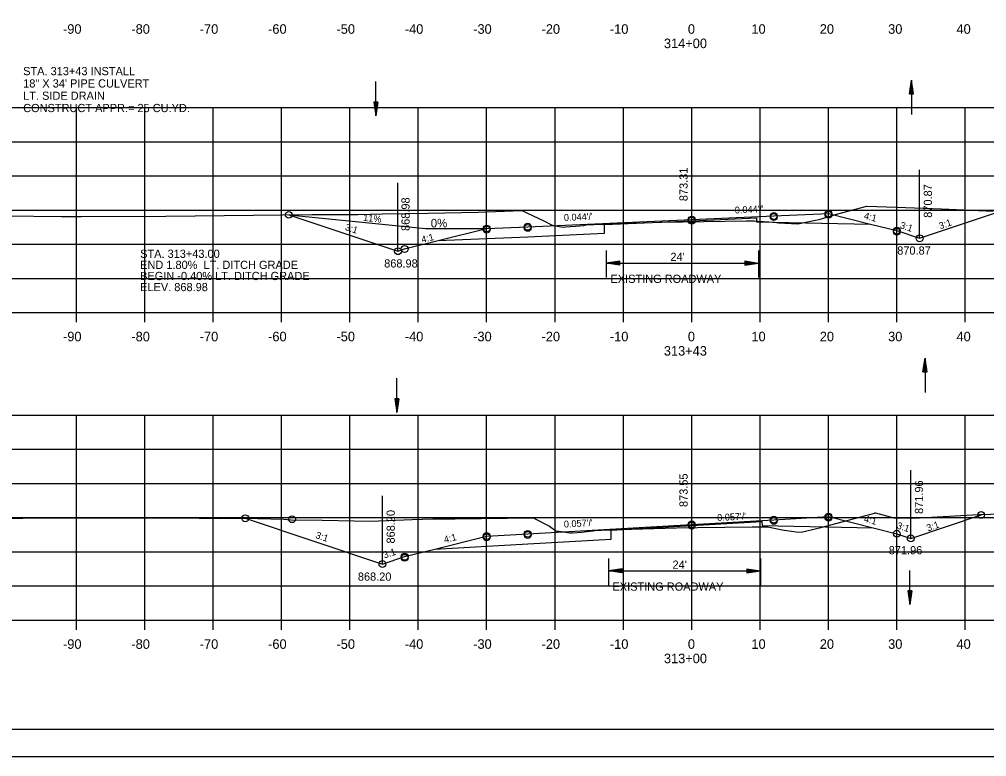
# Model space of a CAD drawing. Extents: x 1486524 to 1499135, y 326561 to 337924.
# Drawn here: x 1488884.5 to 1489026, y 335339.4 to 335447.3 of the extents above; entities that cross this region are included whole.
import ezdxf

# ---------------------------------------------------------------- set-up
doc = ezdxf.new("R2010")
doc.units = 0
for name, color, linetype in [('Default', 7, 'Continuous'), ('E_Const Align', 7, 'Continuous'), ('E_Const Align Station', 7, 'Continuous'), ('E_Ownership Information', 7, 'Continuous'), ('E_Property Line', 7, 'Continuous'), ('E_Proposed ROW and Easements', 7, 'Continuous'), ('E_Proposed ROW Fig Annot', 7, 'Continuous'), ('E_Quarter Calls', 7, 'Continuous'), ('E_Station Offset', 7, 'Continuous'), ('E_Survey Point', 7, 'Continuous'), ('E_Title Sheet', 7, 'Continuous'), ('E_Tract Number', 7, 'Continuous'), ('R_Water Annot', 7, 'Continuous'), ('R_Xsect Elev', 7, 'Continuous'), ('R_Xsect Slope', 7, 'Continuous')]:
    doc.layers.add(name, color=color, linetype=linetype)

msp = doc.modelspace()

# ---------------------------------------------------------------- linework, layer by layer
at = {"layer": 'E_Const Align'}
for p, q in [((1488842.89, 335404.34), (1489122.89, 335404.34)), ((1488892.89, 335402.94), (1488892.89, 335404.34)), ((1488902.89, 335402.94), (1488902.89, 335404.34)), ((1488912.89, 335402.94), (1488912.89, 335404.34)), ((1488922.89, 335402.94), (1488922.89, 335404.34)), ((1488932.89, 335402.94), (1488932.89, 335404.34)), ((1488942.89, 335402.94), (1488942.89, 335404.34)), ((1488952.89, 335402.94), (1488952.89, 335404.34)), ((1488962.89, 335402.94), (1488962.89, 335404.34)), ((1488972.89, 335402.94), (1488972.89, 335404.34)), ((1488982.89, 335402.94), (1488982.89, 335404.34)), ((1488992.89, 335402.94), (1488992.89, 335404.34)), ((1489002.89, 335402.94), (1489002.89, 335404.34)), ((1489012.89, 335402.94), (1489012.89, 335404.34)), ((1489022.89, 335402.94), (1489022.89, 335404.34)), ((1488842.89, 335359.34), (1489122.89, 335359.34)), ((1488892.89, 335357.94), (1488892.89, 335359.34)), ((1488902.89, 335357.94), (1488902.89, 335359.34)), ((1488912.89, 335357.94), (1488912.89, 335359.34)), ((1488922.89, 335357.94), (1488922.89, 335359.34)), ((1488932.89, 335357.94), (1488932.89, 335359.34)), ((1488942.89, 335357.94), (1488942.89, 335359.34)), ((1488952.89, 335357.94), (1488952.89, 335359.34)), ((1488962.89, 335357.94), (1488962.89, 335359.34)), ((1488972.89, 335357.94), (1488972.89, 335359.34)), ((1488982.89, 335357.94), (1488982.89, 335359.34)), ((1488992.89, 335357.94), (1488992.89, 335359.34)), ((1489002.89, 335357.94), (1489002.89, 335359.34)), ((1489012.89, 335357.94), (1489012.89, 335359.34)), ((1489022.89, 335357.94), (1489022.89, 335359.34))]:
    msp.add_line(p, q, dxfattribs=at)
at = {"layer": 'E_Ownership Information'}
for p, q in [((1488842.89, 335434.34), (1489122.89, 335434.34)), ((1488892.89, 335404.34), (1488892.89, 335434.34)), ((1488902.89, 335404.34), (1488902.89, 335434.34)), ((1488912.89, 335404.34), (1488912.89, 335434.34)), ((1488922.89, 335404.34), (1488922.89, 335434.34)), ((1488932.89, 335404.34), (1488932.89, 335434.34)), ((1488942.89, 335404.34), (1488942.89, 335434.34)), ((1488952.89, 335404.34), (1488952.89, 335434.34)), ((1488962.89, 335404.34), (1488962.89, 335434.34)), ((1488972.89, 335404.34), (1488972.89, 335434.34)), ((1488982.89, 335404.34), (1488982.89, 335434.34)), ((1488992.89, 335404.34), (1488992.89, 335434.34)), ((1489002.89, 335404.34), (1489002.89, 335434.34)), ((1489012.89, 335404.34), (1489012.89, 335434.34)), ((1489022.89, 335404.34), (1489022.89, 335434.34)), ((1488842.89, 335429.34), (1489122.89, 335429.34)), ((1488842.89, 335424.34), (1489122.89, 335424.34)), ((1488842.89, 335419.34), (1489122.89, 335419.34)), ((1488842.89, 335414.34), (1489122.89, 335414.34)), ((1488842.89, 335409.34), (1489122.89, 335409.34)), ((1488842.89, 335404.34), (1489122.89, 335404.34)), ((1488842.89, 335389.34), (1489122.89, 335389.34)), ((1488892.89, 335359.34), (1488892.89, 335389.34)), ((1488902.89, 335359.34), (1488902.89, 335389.34)), ((1488912.89, 335359.34), (1488912.89, 335389.34)), ((1488922.89, 335359.34), (1488922.89, 335389.34)), ((1488932.89, 335359.34), (1488932.89, 335389.34)), ((1488942.89, 335359.34), (1488942.89, 335389.34)), ((1488952.89, 335359.34), (1488952.89, 335389.34)), ((1488962.89, 335359.34), (1488962.89, 335389.34)), ((1488972.89, 335359.34), (1488972.89, 335389.34)), ((1488982.89, 335359.34), (1488982.89, 335389.34)), ((1488992.89, 335359.34), (1488992.89, 335389.34)), ((1489002.89, 335359.34), (1489002.89, 335389.34)), ((1489012.89, 335359.34), (1489012.89, 335389.34)), ((1489022.89, 335359.34), (1489022.89, 335389.34)), ((1488842.89, 335384.34), (1489122.89, 335384.34)), ((1488842.89, 335379.34), (1489122.89, 335379.34)), ((1488842.89, 335374.34), (1489122.89, 335374.34)), ((1488842.89, 335369.34), (1489122.89, 335369.34)), ((1488842.89, 335364.34), (1489122.89, 335364.34)), ((1488842.89, 335359.34), (1489122.89, 335359.34))]:
    msp.add_line(p, q, dxfattribs=at)
at = {"layer": 'E_Property Line'}
msp.add_line((1489141.07, 335343.34), (1488824.89, 335343.34), dxfattribs=at)
at = {"layer": 'E_Proposed ROW and Easements'}
for p, q in [((1488970.38, 335413.41), (1488970.38, 335409.48)), ((1488992.66, 335413.41), (1488992.66, 335409.48)), ((1488972.38, 335411.89), (1488970.38, 335411.59)), ((1488972.38, 335411.29), (1488970.38, 335411.59)), ((1488972.38, 335411.84), (1488970.71, 335411.59)), ((1488972.38, 335411.34), (1488970.71, 335411.59)), ((1488972.38, 335411.79), (1488971.06, 335411.59)), ((1488972.38, 335411.4), (1488971.06, 335411.59)), ((1488972.38, 335411.74), (1488971.39, 335411.59)), ((1488972.38, 335411.45), (1488971.39, 335411.59)), ((1488972.38, 335411.69), (1488971.73, 335411.59)), ((1488972.38, 335411.5), (1488971.73, 335411.59)), ((1488972.38, 335411.64), (1488972.06, 335411.59)), ((1488972.38, 335411.55), (1488972.06, 335411.59)), ((1488972.38, 335411.29), (1488972.38, 335411.89)), ((1488990.66, 335411.9), (1488992.66, 335411.6)), ((1488990.66, 335411.9), (1488990.66, 335411.3)), ((1488990.66, 335411.85), (1488992.32, 335411.6)), ((1488990.66, 335411.8), (1488991.98, 335411.6)), ((1488990.66, 335411.75), (1488991.65, 335411.6)), ((1488990.66, 335411.7), (1488991.31, 335411.6)), ((1488990.66, 335411.65), (1488990.97, 335411.6)), ((1488990.66, 335411.3), (1488992.66, 335411.6)), ((1488990.66, 335411.5), (1488991.31, 335411.6)), ((1488990.66, 335411.4), (1488991.98, 335411.6)), ((1488990.66, 335411.35), (1488992.32, 335411.6)), ((1488990.66, 335411.45), (1488991.65, 335411.6)), ((1488990.66, 335411.55), (1488990.97, 335411.6)), ((1488970.69, 335368.37), (1488970.69, 335364.44)), ((1488992.96, 335368.37), (1488992.96, 335364.44)), ((1488972.69, 335366.85), (1488970.69, 335366.55)), ((1488972.69, 335366.8), (1488971.02, 335366.55)), ((1488972.69, 335366.75), (1488971.37, 335366.55)), ((1488972.69, 335366.25), (1488972.69, 335366.85)), ((1488990.96, 335366.86), (1488992.96, 335366.56)), ((1488990.96, 335366.86), (1488990.96, 335366.26)), ((1488990.96, 335366.81), (1488992.63, 335366.56)), ((1488990.96, 335366.76), (1488992.29, 335366.56)), ((1488972.69, 335366.25), (1488970.69, 335366.55)), ((1488972.69, 335366.3), (1488971.02, 335366.55)), ((1488972.69, 335366.35), (1488971.37, 335366.55)), ((1488972.69, 335366.7), (1488971.7, 335366.55)), ((1488972.69, 335366.4), (1488971.7, 335366.55)), ((1488972.69, 335366.65), (1488972.04, 335366.55)), ((1488972.69, 335366.46), (1488972.04, 335366.55)), ((1488972.69, 335366.6), (1488972.37, 335366.55)), ((1488972.69, 335366.51), (1488972.37, 335366.55)), ((1488990.96, 335366.71), (1488991.95, 335366.56)), ((1488990.96, 335366.65), (1488991.61, 335366.56)), ((1488990.96, 335366.6), (1488991.28, 335366.56)), ((1488990.96, 335366.26), (1488992.96, 335366.56)), ((1488990.96, 335366.46), (1488991.61, 335366.56)), ((1488990.96, 335366.36), (1488992.29, 335366.56)), ((1488990.96, 335366.31), (1488992.63, 335366.56)), ((1488990.96, 335366.41), (1488991.95, 335366.56)), ((1488990.96, 335366.51), (1488991.28, 335366.56))]:
    msp.add_line(p, q, dxfattribs=at)
at = {"layer": 'E_Proposed ROW Fig Annot'}
for p, q in [((1489014.73, 335436.34), (1489015.03, 335438.34)), ((1489014.78, 335436.34), (1489015.03, 335438.01)), ((1489014.83, 335436.34), (1489015.03, 335437.67)), ((1489015.33, 335436.34), (1489015.03, 335438.34)), ((1489015.28, 335436.34), (1489015.03, 335438.01)), ((1489015.23, 335436.34), (1489015.03, 335437.67)), ((1489014.73, 335436.34), (1489015.33, 335436.34)), ((1489014.88, 335436.34), (1489015.03, 335437.33)), ((1489014.93, 335436.34), (1489015.03, 335436.99)), ((1489014.98, 335436.34), (1489015.03, 335436.66)), ((1489015.18, 335436.34), (1489015.03, 335437.33)), ((1489015.13, 335436.34), (1489015.03, 335436.99)), ((1489015.08, 335436.34), (1489015.03, 335436.66)), ((1488936.37, 335435.15), (1488936.67, 335433.15)), ((1488936.97, 335435.15), (1488936.37, 335435.15)), ((1488936.42, 335435.15), (1488936.67, 335433.49)), ((1488936.47, 335435.15), (1488936.67, 335433.83)), ((1488936.52, 335435.15), (1488936.67, 335434.16)), ((1488936.57, 335435.15), (1488936.67, 335434.5)), ((1488936.62, 335435.15), (1488936.67, 335434.84)), ((1488936.97, 335435.15), (1488936.67, 335433.15)), ((1488936.77, 335435.15), (1488936.67, 335434.5)), ((1488936.87, 335435.15), (1488936.67, 335433.83)), ((1488936.92, 335435.15), (1488936.67, 335433.49)), ((1488936.82, 335435.15), (1488936.67, 335434.16)), ((1488936.72, 335435.15), (1488936.67, 335434.84)), ((1488970.38, 335411.59), (1488992.66, 335411.6)), ((1489016.72, 335395.67), (1489017.02, 335397.67)), ((1489016.77, 335395.67), (1489017.02, 335397.33)), ((1489016.82, 335395.67), (1489017.02, 335396.99)), ((1489016.87, 335395.67), (1489017.02, 335396.66)), ((1489017.32, 335395.67), (1489017.02, 335397.67)), ((1489017.27, 335395.67), (1489017.02, 335397.33)), ((1489017.22, 335395.67), (1489017.02, 335396.99)), ((1489017.17, 335395.67), (1489017.02, 335396.66)), ((1489016.72, 335395.67), (1489017.32, 335395.67)), ((1489016.92, 335395.67), (1489017.02, 335396.32)), ((1489016.97, 335395.67), (1489017.02, 335395.98)), ((1489017.11, 335395.67), (1489017.02, 335396.32)), ((1489017.06, 335395.67), (1489017.02, 335395.98)), ((1488939.44, 335391.73), (1488939.74, 335389.73)), ((1488940.04, 335391.73), (1488939.44, 335391.73)), ((1488939.49, 335391.73), (1488939.74, 335390.06)), ((1488939.54, 335391.73), (1488939.74, 335390.41)), ((1488939.59, 335391.73), (1488939.74, 335390.74)), ((1488939.64, 335391.73), (1488939.74, 335391.08)), ((1488939.69, 335391.73), (1488939.74, 335391.41)), ((1488940.04, 335391.73), (1488939.74, 335389.73)), ((1488939.83, 335391.73), (1488939.74, 335391.08)), ((1488939.94, 335391.73), (1488939.74, 335390.41)), ((1488939.99, 335391.73), (1488939.74, 335390.06)), ((1488939.89, 335391.73), (1488939.74, 335390.74)), ((1488939.78, 335391.73), (1488939.74, 335391.41)), ((1488970.69, 335366.55), (1488992.96, 335366.56)), ((1489014.49, 335363.62), (1489014.79, 335361.62)), ((1489015.09, 335363.62), (1489014.49, 335363.62)), ((1489014.54, 335363.62), (1489014.79, 335361.95)), ((1489014.59, 335363.62), (1489014.79, 335362.29)), ((1489014.64, 335363.62), (1489014.79, 335362.63)), ((1489014.69, 335363.62), (1489014.79, 335362.97)), ((1489014.74, 335363.62), (1489014.79, 335363.3)), ((1489015.09, 335363.62), (1489014.79, 335361.62)), ((1489014.89, 335363.62), (1489014.79, 335362.97)), ((1489014.99, 335363.62), (1489014.79, 335362.29)), ((1489015.04, 335363.62), (1489014.79, 335361.95)), ((1489014.94, 335363.62), (1489014.79, 335362.63)), ((1489014.84, 335363.62), (1489014.79, 335363.3))]:
    msp.add_line(p, q, dxfattribs=at)
at = {"layer": 'E_Quarter Calls'}
msp.add_line((1488812.48, 335339.37), (1489145.82, 335339.37), dxfattribs=at)
for points in [[(1488812.48, 335552.7), (1489145.82, 335552.7), (1489145.82, 335339.36), (1488812.48, 335339.36)], [(1489058.81, 335548.8), (1489058.81, 335538.92), (1489094.54, 335538.92), (1489094.54, 335536), (1489117.74, 335536), (1489117.74, 335511.67), (1489141.07, 335511.67), (1489141.07, 335343.34), (1488824.89, 335343.34), (1488824.89, 335548.8)]]:
    msp.add_lwpolyline(points, close=True, dxfattribs=at)
for centre in [(1488923.94, 335418.65), (1489002.89, 335418.84), (1489002.89, 335418.84), (1489002.89, 335418.67), (1488982.89, 335417.96), (1488982.89, 335417.96), (1488982.89, 335417.79), (1488994.89, 335418.49), (1488994.89, 335418.49), (1488994.89, 335418.32), (1488952.89, 335416.65), (1488952.89, 335416.65), (1488952.89, 335416.48), (1488958.89, 335416.91), (1488958.89, 335416.91), (1488958.89, 335416.74), (1489012.89, 335416.34), (1489012.89, 335416.34), (1489012.89, 335416.17), (1489016.23, 335415.22), (1488939.92, 335413.32), (1488940.89, 335413.65), (1488940.89, 335413.65), (1489025.23, 335374.74), (1488917.58, 335374.24), (1488924.45, 335374.11), (1488982.89, 335373.34), (1488982.89, 335373.34), (1488994.89, 335374.03), (1488994.89, 335374.03), (1488994.89, 335373.86), (1489002.89, 335374.49), (1489002.89, 335374.49), (1489002.89, 335374.32), (1488958.89, 335371.97), (1488958.89, 335371.97), (1488982.89, 335373.17), (1489012.89, 335371.99), (1488952.89, 335371.63), (1488952.89, 335371.63), (1488952.89, 335371.46), (1488958.89, 335371.8), (1489014.93, 335371.3), (1488940.89, 335368.63), (1488940.89, 335368.63), (1488940.89, 335368.46), (1488937.65, 335367.55)]:
    msp.add_circle(centre, 0.5, dxfattribs=at)
at = {"layer": 'E_Station Offset'}
for p, q in [((1488923.94, 335418.65), (1488943.93, 335416.65)), ((1488943.93, 335416.65), (1488952.93, 335416.65))]:
    msp.add_line(p, q, dxfattribs=at)
at = {"layer": 'E_Survey Point'}
for points in [[(1488945.81, 335414.88), (1488958.89, 335415.45), (1488970.12, 335415.95), (1488970.12, 335417.24), (1488982.89, 335417.79), (1488992.37, 335418.21), (1488992.38, 335417.63), (1489009.06, 335417.29)], [(1488945.31, 335369.74), (1488958.89, 335370.51), (1488971.1, 335371.21), (1488971.1, 335372.5), (1488982.89, 335373.18), (1488993.16, 335373.76), (1488993.17, 335373.18), (1489009.41, 335372.85)]]:
    msp.add_lwpolyline(points, dxfattribs=at)
at = {"layer": 'E_Title Sheet'}
for points in [[(1488923.94, 335418.65), (1488939.92, 335413.32), (1488940.89, 335413.65), (1488945.81, 335414.88), (1488952.89, 335416.65), (1488958.89, 335416.91), (1488982.89, 335417.96), (1488994.89, 335418.49), (1489002.89, 335418.84), (1489009.06, 335417.29), (1489012.89, 335416.34), (1489016.23, 335415.22), (1489028.21, 335419.21)], [(1488917.58, 335374.24), (1488937.65, 335367.55), (1488940.89, 335368.63), (1488945.31, 335369.74), (1488952.89, 335371.63), (1488958.89, 335371.97), (1488982.89, 335373.34), (1488994.89, 335374.03), (1489002.89, 335374.49), (1489009.41, 335372.85), (1489012.89, 335371.99), (1489014.93, 335371.3), (1489025.23, 335374.74)]]:
    msp.add_lwpolyline(points, dxfattribs=at)
at = {"layer": 'E_Tract Number'}
for points in [[(1488882.57, 335418.48), (1488890.7, 335418.39), (1488892.99, 335418.4), (1488893.58, 335418.4), (1488905.95, 335418.45), (1488927.32, 335418.71), (1488931.42, 335418.69), (1488934.04, 335418.72), (1488937.65, 335418.78), (1488944.33, 335418.89), (1488951.65, 335419.04), (1488958.04, 335419.28), (1488961.26, 335417.76), (1488962.37, 335417.17), (1488962.69, 335417.1), (1488964.08, 335416.85), (1488964.43, 335416.89), (1488965.88, 335417), (1488967.09, 335417.11), (1488967.47, 335417.18), (1488968.44, 335417.23), (1488968.59, 335417.24), (1488970.25, 335417.29), (1488979.81, 335417.61), (1488981.61, 335417.63), (1488990.84, 335417.78), (1488991.07, 335417.78), (1488992.07, 335417.75), (1488992.58, 335417.7), (1488994.99, 335417.58), (1488995.57, 335417.5), (1488998.43, 335417.32), (1489001.01, 335417.87), (1489001.51, 335417.96), (1489004.25, 335418.81), (1489008.49, 335419.94), (1489012.84, 335419.78), (1489019.44, 335419.51), (1489026.98, 335419.2)], [(1488874.81, 335374.11), (1488888.44, 335374.31), (1488891.92, 335374.33), (1488901.64, 335374.32), (1488907.92, 335374.31), (1488913.78, 335374.22), (1488917.47, 335374.25), (1488923.22, 335374.1), (1488924.27, 335374.02), (1488928.85, 335373.98), (1488935.86, 335373.8), (1488941.98, 335374.08), (1488945.01, 335374.18), (1488948.3, 335374.18), (1488959.67, 335374.31), (1488962.06, 335373.09), (1488963.02, 335372.43), (1488963.45, 335372.36), (1488965.07, 335372.1), (1488965.47, 335372.13), (1488966.79, 335372.2), (1488967.17, 335372.25), (1488968.44, 335372.43), (1488968.73, 335372.45), (1488969.67, 335372.5), (1488972.4, 335372.59), (1488980.67, 335372.86), (1488983.71, 335372.9), (1488991.73, 335373.01), (1488992.23, 335373), (1488992.61, 335372.99), (1488994.01, 335373), (1488996.1, 335372.57), (1488998.19, 335372.28), (1488998.89, 335372.22), (1488999.55, 335372.36), (1489001.96, 335372.92), (1489009.61, 335375), (1489009.68, 335375.02), (1489009.76, 335375.02), (1489012.47, 335374.33), (1489016.22, 335374.31), (1489024.03, 335374.76), (1489024.87, 335374.8), (1489025.15, 335374.81), (1489025.37, 335374.82), (1489035.16, 335375.21)]]:
    msp.add_lwpolyline(points, dxfattribs=at)
at = {"layer": 'R_Water Annot'}
for p, q in [((1488936.67, 335433.15), (1488936.67, 335438.15)), ((1489015.03, 335438.34), (1489015.03, 335433.34)), ((1489017.02, 335397.67), (1489017.02, 335392.67)), ((1488939.74, 335389.73), (1488939.74, 335394.73)), ((1489014.79, 335361.62), (1489014.79, 335366.62))]:
    msp.add_line(p, q, dxfattribs=at)
at = {"layer": 'R_Xsect Elev'}
for p, q in [((1488982.89, 335417.65), (1488982.89, 335427.65)), ((1489016.23, 335415.22), (1489016.23, 335425.22)), ((1488939.92, 335413.32), (1488939.92, 335423.32)), ((1488982.89, 335372.89), (1488982.89, 335382.89)), ((1489014.93, 335371.3), (1489014.93, 335381.3)), ((1488937.65, 335367.55), (1488937.65, 335377.55))]:
    msp.add_line(p, q, dxfattribs=at)

# ---------------------------------------------------------------- texts
at = {"layer": 'Default'}
for s, p in [('STA. 313+43 INSTALL', (1488885.09, 335439.08)), ('18" X 34\' PIPE CULVERT', (1488885.09, 335437.28)), ('LT. SIDE DRAIN', (1488885.09, 335435.48)), ('CONSTRUCT APPR.= 25 CU.YD.', (1488885.09, 335433.68))]:
    msp.add_text(s, height=1.2, dxfattribs=at).set_placement(p)
at = {"layer": 'E_Const Align Station'}
for s, p in [('-90', (1488890.92, 335445.14)), ('-80', (1488900.92, 335445.14)), ('-70', (1488910.92, 335445.14)), ('-60', (1488920.92, 335445.14)), ('-50', (1488930.92, 335445.14)), ('-40', (1488940.92, 335445.14)), ('-30', (1488950.92, 335445.14)), ('-20', (1488960.92, 335445.14)), ('-10', (1488970.92, 335445.14)), ('0', (1488982.32, 335445.14)), ('10', (1488991.62, 335445.14)), ('20', (1489001.62, 335445.14)), ('30', (1489011.62, 335445.14)), ('40', (1489021.62, 335445.14)), ('314+00', (1488978.82, 335443.04)), ('-90', (1488890.92, 335400.14)), ('-80', (1488900.92, 335400.14)), ('-70', (1488910.92, 335400.14)), ('-60', (1488920.92, 335400.14)), ('-50', (1488930.92, 335400.14)), ('-40', (1488940.92, 335400.14)), ('-30', (1488950.92, 335400.14)), ('-20', (1488960.92, 335400.14)), ('-10', (1488970.92, 335400.14)), ('0', (1488982.32, 335400.14)), ('10', (1488991.62, 335400.14)), ('20', (1489001.62, 335400.14)), ('30', (1489011.62, 335400.14)), ('40', (1489021.62, 335400.14)), ('313+43', (1488978.81, 335398.04)), ('-90', (1488890.92, 335355.14)), ('-80', (1488900.92, 335355.14)), ('-70', (1488910.92, 335355.14)), ('-60', (1488920.92, 335355.14)), ('-50', (1488930.92, 335355.14)), ('-40', (1488940.92, 335355.14)), ('-30', (1488950.92, 335355.14)), ('-20', (1488960.92, 335355.14)), ('-10', (1488970.92, 335355.14)), ('0', (1488982.32, 335355.14)), ('10', (1488991.62, 335355.14)), ('20', (1489001.62, 335355.14)), ('30', (1489011.62, 335355.14)), ('40', (1489021.62, 335355.14)), ('313+00', (1488978.82, 335353.04))]:
    msp.add_text(s, height=1.4, dxfattribs=at).set_placement(p)
at = {"layer": 'E_Proposed ROW Fig Annot'}
msp.add_text('11%', height=1, rotation=353.8171, dxfattribs=at).set_placement((1488934.79, 335417.78))
for s, p in [('STA. 313+43.00', (1488902.2, 335412.35)), ("24'", (1488979.77, 335411.9)), ('END 1.80%  LT. DITCH GRADE', (1488902.2, 335410.73)), ('BEGIN -0.40% LT. DITCH GRADE', (1488902.2, 335409.1)), ('EXISTING ROADWAY', (1488971, 335408.69)), ('ELEV. 868.98', (1488902.2, 335407.48)), ("24'", (1488980.08, 335366.86)), ('EXISTING ROADWAY', (1488971.3, 335363.65))]:
    msp.add_text(s, height=1.2, dxfattribs=at).set_placement(p)
at = {"layer": 'E_Station Offset'}
msp.add_text('0%', height=1.25, dxfattribs=at).set_placement((1488944.71, 335416.81))
at = {"layer": 'R_Xsect Elev'}
for s, p in [('873.31', (1488982.29, 335420.65)), ('870.87', (1489018.03, 335418.22)), ('868.98', (1488941.62, 335416.29)), ('873.55', (1488982.29, 335375.89)), ('871.96', (1489016.73, 335374.88)), ('868.20', (1488939.45, 335370.55))]:
    msp.add_text(s, height=1.2, rotation=90, dxfattribs=at).set_placement(p)
for s, p in [('870.87', (1489012.95, 335412.83)), ('868.98', (1488937.9, 335410.94)), ('871.96', (1489011.71, 335368.97)), ('868.20', (1488934.05, 335365.11))]:
    msp.add_text(s, height=1.2, dxfattribs=at).set_placement(p)
at = {"layer": 'R_Xsect Slope'}
for s, rotation, p in [("0.044'/'", 2.505, (1488989.21, 335418.84)), ("0.044'/'", 2.5053, (1488964.21, 335417.74)), ('4:1', 345.9638, (1489008.01, 335418.07)), ('3:1', 19.3446, (1489019.25, 335416.52)), ('3:1', 341.5651, (1488932.09, 335416.46)), ('3:1', 341.5651, (1489013.27, 335416.73)), ('4:1', 14.0362, (1488943.46, 335414.52)), ("0.057'/'", 3.272, (1488964.21, 335372.88)), ("0.057'/'", 3.2719, (1488986.64, 335373.83)), ('4:1', 345.9638, (1489008.01, 335373.72)), ('3:1', 341.5651, (1489012.8, 335372.78)), ('3:1', 19.3446, (1489017.44, 335372.3)), ('3:1', 341.5651, (1488927.77, 335371.37)), ('4:1', 14.0362, (1488946.76, 335370.61)), ('3:1', 18.4349, (1488937.94, 335368.35))]:
    msp.add_text(s, height=1, rotation=rotation, dxfattribs=at).set_placement(p)

doc.saveas('drawing.dxf')
